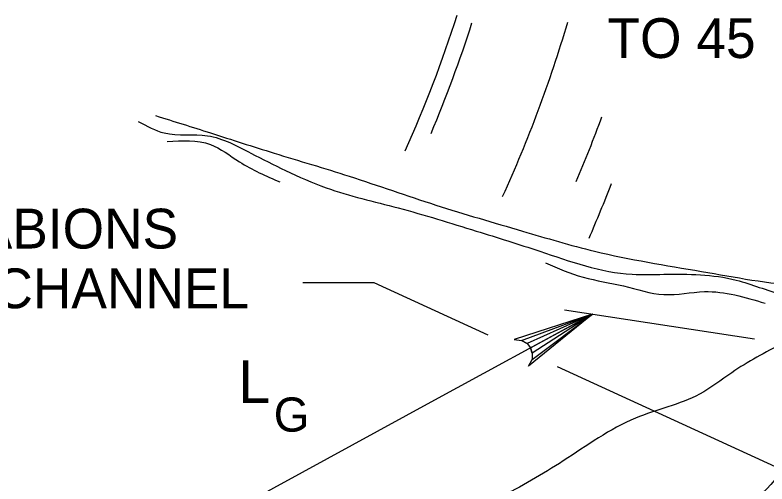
# Model space of a CAD drawing. Extents: x 3 to 3592, y -602 to 1171.
# Drawn here: x 563.9 to 629.9, y 1067.6 to 1108.9 of the extents above; entities that cross this region are included whole.
import ezdxf

# ---------------------------------------------------------------- set-up
doc = ezdxf.new("R2010")
doc.units = 0
doc.layers.add('2', color=7, linetype='Continuous')
doc.layers.add('3', color=7, linetype='Continuous')

msp = doc.modelspace()

# ---------------------------------------------------------------- linework, layer by layer
at = {"layer": '2'}
for p, q in [((589.2, 1085.37), (595.42, 1085.37)), ((595.42, 1085.37), (605.447, 1080.762)), ((612.157, 1082.961), (628.844, 1080.394)), ((614.633, 1082.58), (600.424, 1074.83)), ((611.518, 1077.971), (631.363, 1068.851)), ((600.424, 1074.83), (573.383, 1060.08))]:
    msp.add_line(p, q, dxfattribs=at)
msp.add_lwpolyline([(614.633, 1082.58), (609.013, 1077.992), (609.314, 1078.59), (614.633, 1082.58), (609.333, 1079.145), (609.176, 1079.604), (614.633, 1082.58), (608.875, 1079.985), (608.398, 1080.269), (614.633, 1082.58), (607.733, 1080.34), (608.398, 1080.269), (608.875, 1079.985), (609.176, 1079.604), (609.333, 1079.145), (609.314, 1078.59)], dxfattribs=at)
for centre, start, end in [((490.99, 1144.808), 335.93338, 342.17208), ((492.258, 1144.047), 337.15351, 342.20981), ((499.866, 1141.511), 335.54374, 343.53588), ((505.192, 1140.243), 336.92568, 339.90683), ((506.713, 1136.185), 336.43719, 338.96807)]:
    msp.add_arc(centre, 117.398, start, end, dxfattribs=at)
for points in [[(576.265, 1100.024), (581.083, 1098.502), (586.663, 1096.727), (593.256, 1094.698), (600.865, 1092.162), (608.473, 1089.88), (614.813, 1088.104), (624.197, 1086.329), (633.073, 1085.061), (639.92, 1085.061)], [(574.743, 1099.517), (577.026, 1098.502), (580.83, 1098.249), (584.634, 1096.727), (587.677, 1095.205), (591.228, 1093.684), (597.568, 1091.909), (604.415, 1089.88), (609.995, 1088.104), (618.11, 1086.076), (620.9, 1086.076), (627.24, 1085.568), (631.298, 1084.3), (637.638, 1083.793)], [(577.279, 1097.742), (581.083, 1097.488), (583.619, 1095.966), (587.17, 1094.191)], [(610.502, 1087.09), (613.799, 1085.822), (617.349, 1085.061), (620.9, 1084.3), (624.45, 1084.554), (629.776, 1083.539)], [(631.312, 1080.014), (626.851, 1077.431), (624.033, 1075.553), (618.398, 1073.44), (612.058, 1069.683), (606.423, 1066.395), (596.796, 1061.23), (590.062, 1057.514)], [(663.812, 1075.014), (659.351, 1072.431), (656.533, 1070.553), (650.898, 1068.44), (644.558, 1064.683), (638.923, 1061.395), (629.296, 1056.23), (622.562, 1052.514)], [(638.686, 1074.809), (633.089, 1071.728), (630.621, 1068.024), (623.375, 1063.481)]]:
    msp.add_spline(points, degree=3, dxfattribs=at)

# ---------------------------------------------------------------- texts
at = {"layer": '3'}
for s, height, p in [('TO 45', 3.5, (615.94, 1105.085)), ('SLOPE GABIONS', 3.5, (540.003, 1088.343)), ('TOWARD CHANNEL', 3.5, (540.003, 1083.093)), ('L', 3.75, (583.528, 1074.762)), ('G', 2.999, (586.635, 1072.251))]:
    msp.add_text(s, height=height, dxfattribs=at).set_placement(p)

doc.saveas('drawing.dxf')
